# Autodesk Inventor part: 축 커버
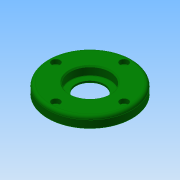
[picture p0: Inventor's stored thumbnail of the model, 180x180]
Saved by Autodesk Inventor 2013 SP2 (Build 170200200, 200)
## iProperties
Created: 2015-10
Part Number: 축 커버
Document SubType Name: Modeling
Designer: mdu
Density: 2.71 g/cm^3
Material: 알루미늄 6061
Mass: 110.724 g
Surface Area: 133.807 cm^2
Volume: 40.8575 cm^3
Author: mdu
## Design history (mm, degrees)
sketch "스케치1"
  geometry: C1 r 40 at (0, 0) reference; C2 r 26 at (0, 0) reference; 1 further point
  node "참조1"
  node "참조2"
extrude "돌출1" new body sketch "스케치1" distance "d0" = 10; taper "d1" = 0 deg
extrude "돌출2" join sketch "스케치1" distance "d2" = 3; taper "d3" = 0 deg
hole "구멍1" diameter "d6" = 27; stored, may be unused: countersink angle "d10" = 90 deg, drill point angle "d12" = 118 deg; dims "d7" = 6, "d8" = 38, "d9" = 8.3, "d11" = 8, "d31" = 10, "d32" = 10
sketch "스케치2"
  geometry: C1 r 20 at (0, 0); 1 further point
  constraints: 1 centre point, 1 coincident
  dimensions: "d13" = 40 diameter of C1
extrude "돌출3" cut sketch "스케치2" distance "d14" = 3; taper "d15" = 0 deg
sketch "스케치3"
  geometry: C1 r 1.621 at (0, 32.5) reference; 1 further point
hole "구멍2" sketch "스케치3" at (0, 32.5) diameter "d16" = 4.5; stored, may be unused: countersink angle "d20" = 90 deg, drill point angle "d22" = 118 deg; dims "d17" = 6, "d18" = 8, "d19" = 4.4, "d21" = 8
fillet "모깎기1" dims "d26" = 3, "d27" = 0.3
chamfer "모따기1" distance "d28" = 1; stored, may be unused: second distance "d29" = 2, angle "d30" = 45 deg
node "솔리드1"
pattern_circular "원형 패턴1" dims angle "d24" = 360 deg
node "참조3"
